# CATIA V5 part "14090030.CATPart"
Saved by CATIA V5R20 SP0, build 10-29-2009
Part number: 14090030
Definition: NONE
Nomenclature: 14090030
Source: Unknown
Description: 14090030
Bounding box of the stored display mesh (mm): x -15 to 60, y -59 to 49.1, z -49.1 to 49.1
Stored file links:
  C:\Users\Utente\Desktop\IO LAVORO\3D X SITO CF\X SITO\PLASTICA\RF2\14090030.CATPart
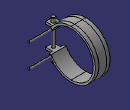
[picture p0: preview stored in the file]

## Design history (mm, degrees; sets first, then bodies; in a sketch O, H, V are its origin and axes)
Body1 "14090030" (main body)
  Solid1: solid without history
